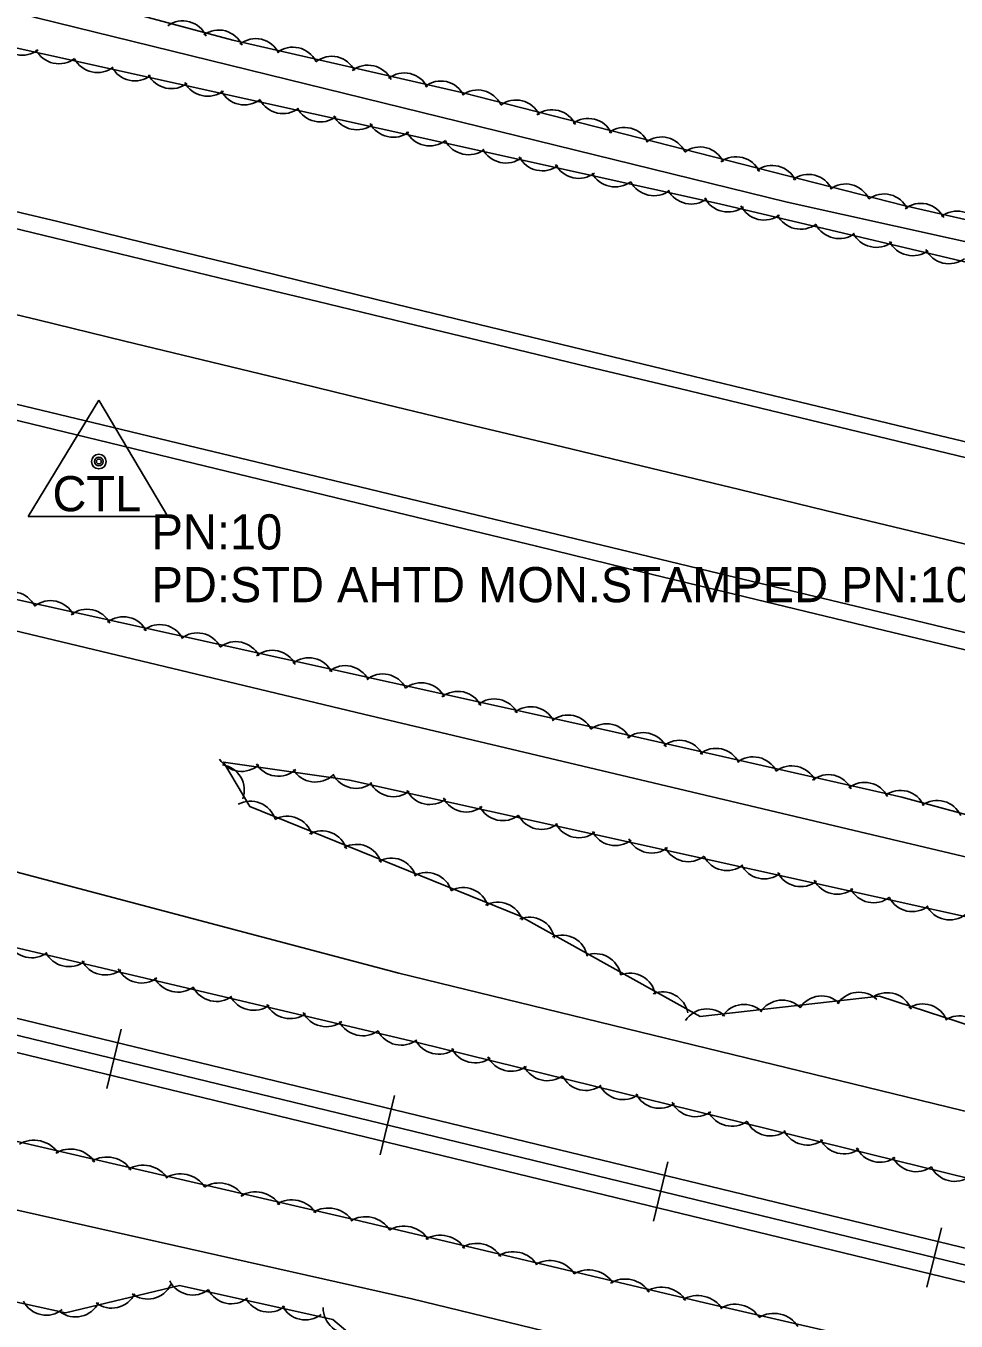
# Model space of a CAD drawing. Extents: x 1441650 to 1491889, y 345904 to 358319.
# Drawn here: x 1451853.3 to 1451985.6, y 352945.7 to 353129.9 of the extents above; entities that cross this region are included whole.
import ezdxf

# ---------------------------------------------------------------- set-up
doc = ezdxf.new("R2010")
doc.units = 0
for name, color, linetype in [('S_EDGE_PAVEMENT', 7, 'Continuous'), ('S_PAVEMENT_CROWN', 7, 'Continuous'), ('S_PRIMARY_CTL', 7, 'Continuous'), ('S_PRIMARY_CTL_ANNOT', 7, 'Continuous'), ('S_RAILROAD', 7, 'Continuous'), ('S_SHOULDER', 7, 'Continuous'), ('S_STREAM', 7, 'Continuous'), ('S_TREE', 7, 'Continuous')]:
    doc.layers.add(name, color=color, linetype=linetype)

msp = doc.modelspace()

# ---------------------------------------------------------------- linework, layer by layer
at = {"layer": 'S_EDGE_PAVEMENT'}
for points in [[(1451783.27, 353117.48), (1451795.88, 353114.44), (1451808.49, 353111.4), (1451820.7, 353108.49), (1451832.9, 353105.58), (1451845.11, 353102.67), (1451857.31, 353099.75), (1451869.83, 353096.73), (1451882.35, 353093.7), (1451894.87, 353090.67), (1451907.38, 353087.64), (1451920.35, 353084.53), (1451933.31, 353081.42), (1451946.28, 353078.32), (1451959.25, 353075.21), (1451982.98, 353069.48), (1452006.71, 353063.75), (1452019.76, 353060.6), (1452032.81, 353057.44), (1452045.86, 353054.28), (1452058.91, 353051.13), (1452072, 353047.96), (1452085.09, 353044.79), (1452098.18, 353041.61)], [(1451777.98, 353093.92), (1451790.47, 353090.88), (1451802.97, 353087.85), (1451815.21, 353084.91), (1451827.46, 353081.98), (1451839.71, 353079.05), (1451851.96, 353076.11), (1451864.17, 353073.17), (1451876.38, 353070.23), (1451888.6, 353067.29), (1451900.81, 353064.35), (1451913.59, 353061.27), (1451926.38, 353058.2), (1451939.16, 353055.12), (1451951.95, 353052.04), (1451975.89, 353046.27), (1451999.84, 353040.51), (1452013.23, 353037.27), (1452026.61, 353034.04), (1452040, 353030.81), (1452053.39, 353027.58), (1452066.24, 353024.5), (1452079.1, 353021.43), (1452091.95, 353018.36)]]:
    msp.add_lwpolyline(points, dxfattribs=at)
at = {"layer": 'S_PAVEMENT_CROWN'}
msp.add_lwpolyline([(1451780.05, 353106.21), (1451792.45, 353103.16), (1451804.86, 353100.12), (1451817.4, 353097.11), (1451829.94, 353094.1), (1451842.48, 353091.09), (1451855.02, 353088.08), (1451867.4, 353085.07), (1451879.77, 353082.07), (1451892.14, 353079.07), (1451904.51, 353076.07), (1451917.08, 353073.04), (1451929.66, 353070.01), (1451942.23, 353066.98), (1451954.8, 353063.95), (1451967.03, 353061), (1451979.27, 353058.05), (1451991.5, 353055.1)], dxfattribs=at)
at = {"layer": 'S_PRIMARY_CTL'}
for p, q in [((1451863.71, 353076.65), (1451853.68, 353060.13)), ((1451863.71, 353076.65), (1451873.54, 353060.13)), ((1451853.68, 353060.13), (1451873.54, 353060.13))]:
    msp.add_line(p, q, dxfattribs=at)
for radius in [1.04, 0.609, 0.344]:
    msp.add_circle((1451863.71, 353067.94), radius, dxfattribs=at)
at = {"layer": 'S_RAILROAD'}
for p, q in [((1451864.85, 352978.8), (1451866.89, 352987.23)), ((1451866.42, 352985.29), (1451866.4, 352985.19)), ((1451865.31, 352980.71), (1451865.32, 352980.75)), ((1451903.73, 352969.38), (1451905.77, 352977.81)), ((1451905.3, 352975.87), (1451905.28, 352975.77)), ((1451904.19, 352971.29), (1451904.2, 352971.33)), ((1451942.61, 352959.96), (1451944.65, 352968.39)), ((1451944.18, 352966.45), (1451944.15, 352966.35)), ((1451943.07, 352961.87), (1451943.08, 352961.91)), ((1451981.48, 352950.55), (1451983.53, 352958.98)), ((1451983.06, 352957.03), (1451983.03, 352956.93)), ((1451981.95, 352952.45), (1451981.96, 352952.49))]:
    msp.add_line(p, q, dxfattribs=at)
for points in [[(1452391.27, 352858.13), (1451315.37, 353118.79)], [(1452390.72, 352855.86), (1451314.82, 353116.52)], [(1452390.16, 352853.56), (1451314.26, 353114.21)], [(1451865.9, 352983.01), (1451865.87, 352983.02)], [(1451904.78, 352973.59), (1451904.75, 352973.6)], [(1451943.66, 352964.17), (1451943.63, 352964.18)], [(1451982.53, 352954.75), (1451982.51, 352954.76)]]:
    msp.add_lwpolyline(points, dxfattribs=at)
at = {"layer": 'S_SHOULDER'}
for points in [[(1451784.12, 353119.66), (1451796.45, 353116.64), (1451808.79, 353113.61), (1451821.06, 353110.72), (1451833.33, 353107.84), (1451845.59, 353104.95), (1451857.86, 353102.06), (1451870.4, 353099), (1451882.94, 353095.94), (1451895.48, 353092.87), (1451908.01, 353089.81), (1451920.95, 353086.67), (1451933.88, 353083.53), (1451946.81, 353080.4), (1451959.74, 353077.26), (1451983.41, 353071.6), (1452007.08, 353065.94), (1452020.17, 353062.81), (1452033.26, 353059.68), (1452046.34, 353056.55), (1452059.43, 353053.42), (1452072.45, 353050.18), (1452085.47, 353046.94), (1452098.49, 353043.7)], [(1451776.78, 353092.03), (1451789.4, 353088.96), (1451802.02, 353085.89), (1451814.3, 353082.92), (1451826.59, 353079.95), (1451838.88, 353076.98), (1451851.16, 353074.01), (1451863.47, 353071.03), (1451875.77, 353068.05), (1451888.08, 353065.07), (1451900.38, 353062.09), (1451913.16, 353058.99), (1451925.93, 353055.89), (1451938.71, 353052.79), (1451951.48, 353049.7), (1451975.44, 353043.94), (1451999.4, 353038.19), (1452012.81, 353034.93), (1452026.22, 353031.67), (1452039.63, 353028.41), (1452053.04, 353025.15), (1452065.84, 353022.05), (1452078.65, 353018.96), (1452091.46, 353015.87)]]:
    msp.add_lwpolyline(points, dxfattribs=at)
at = {"layer": 'S_STREAM'}
for points in [[(1452445.19, 352960.92), (1452448.5, 352972.75), (1452448.23, 352981.93), (1452444.57, 352990.17), (1452433.3, 352993.25), (1452415.41, 352997.26), (1452378.65, 353003.82), (1452324.67, 353015.77), (1452282.93, 353026.78), (1452238.99, 353039.11), (1452155.9, 353057.5), (1452105.48, 353068.81), (1452050.85, 353084.26), (1452000.32, 353096.23), (1451961.6, 353104.8), (1451854.91, 353131.04), (1451766.04, 353157.21)], [(1452109.57, 352946.22), (1452091.57, 352950.96), (1451986.3, 352975.72), (1451906.35, 352995.19), (1451767.48, 353031.94), (1451736.48, 353040.82), (1451750.21, 353055.92), (1451749.26, 353065.31), (1451760.74, 353064.8), (1451835.77, 353047.72), (1451901.35, 353032.04), (1451989.35, 353011.18), (1452041.05, 352997.24), (1452069.23, 352991.2), (1452108.22, 352979.84), (1452119.37, 352976.87)], [(1451761.2, 352984.03), (1451829.92, 352966.49), (1451908.23, 352948.92), (1451988.74, 352929.34), (1452105.17, 352903.77), (1452208.98, 352879), (1452288.64, 352859.53), (1452296.9, 352854.48), (1452309.22, 352851.75), (1452341.4, 352846.85)]]:
    msp.add_lwpolyline(points, dxfattribs=at)
at = {"layer": 'S_TREE'}
for points in [[(1451842.5, 353138.67), (1451882.78, 353127.85), (1451915.54, 353120.36), (1451978.21, 353104.35), (1452002.07, 353098.89), (1452031.98, 353100.97), (1452056.87, 353104.1), (1452066.02, 353098.43), (1452087.42, 353079.53), (1452116.54, 353072.49)], [(1452429.49, 352965.49), (1452437.88, 352969.07), (1452439.81, 352977.76), (1452437.34, 352984.74), (1452427.24, 352990.22), (1452405.5, 352995.03), (1452379.5, 353000.79), (1452338.14, 353009.4), (1452310.5, 353013.5), (1452296.75, 353015.27), (1452257.56, 353023.53), (1452218.85, 353038.77), (1452176.21, 353048.21), (1452120.8, 353061.85), (1452077.66, 353072.61), (1452041.75, 353083.37), (1451951.96, 353104.58), (1451836.47, 353130.15), (1451825.19, 353132.83)], [(1452399.14, 352860.23), (1452392.79, 352867.03), (1452382.12, 352869.59), (1452327.3, 352883.47), (1452173.6, 352920.35), (1452113.09, 352935.02), (1451909.03, 352985.34), (1451768.73, 353018.48), (1451597.59, 353062.21), (1451520.63, 353079.57), (1451497.6, 353087.01), (1451451.58, 353107.05), (1451431.16, 353111.57), (1451407.97, 353109.12), (1451350.29, 353121.94)], [(1451327.8, 353097.43), (1451402.02, 353075.91), (1451483.15, 353063.22), (1451576.93, 353036.02), (1451646.54, 353020.05), (1451689.99, 353010.43), (1451796.02, 352984.25), (1451899.97, 352960.18), (1451949.9, 352948.34), (1452006.53, 352935.3), (1452073.14, 352918.73), (1452124.03, 352905.6), (1452167.72, 352893.63), (1452197.97, 352887.99), (1452238.01, 352878.56), (1452281.14, 352868.99), (1452322.62, 352858.1), (1452348, 352852.48), (1452371.02, 352846.3), (1452385.26, 352842.85), (1452392.41, 352843.39), (1452396.82, 352844.8), (1452398.6, 352846.57)], [(1451756.76, 353072.92), (1451807.16, 353058.25), (1451866.54, 353045.1), (1451936.11, 353029.7), (1451977.89, 353020.21), (1452015.38, 353010.02), (1452054.5, 353001.3), (1452108.24, 352989.27)], [(1452103.73, 352977.64), (1452080.41, 352979.97), (1452042.94, 352989.96), (1452000.57, 353000.22), (1451939.2, 353013.81), (1451899.38, 353022.62), (1451881.43, 353025.21), (1451885.19, 353018.89), (1451923.55, 353003.35), (1451949.24, 352989.05), (1451974.75, 352991.94), (1451992.76, 352986.08), (1452003.91, 352976.56), (1452027.47, 352979.69), (1452048.56, 352975.18), (1452071.11, 352968.43), (1452109.87, 352950.96)], [(1452091.94, 352900.54), (1452069.93, 352896.14), (1452043.61, 352882.16), (1452020.94, 352887.17), (1451990.24, 352893.97), (1451963.33, 352905.38), (1451917.06, 352921.58), (1451910.69, 352934.41), (1451896.97, 352945.96), (1451875.2, 352950.78), (1451858.99, 352946.93), (1451844.89, 352949.99), (1451833.41, 352962.9), (1451811.35, 352963.14), (1451805.02, 352950.99), (1451762.83, 352955.93)]]:
    msp.add_lwpolyline(points, dxfattribs=at)
for centre, major_axis, ratio, start_param, end_param in [((1451875.66, 353126.94), (-1.09, 3.48), 0.995778, 4.831799, 6.605), ((1451880.77, 353125.64), (-1.09, 3.48), 0.995778, 4.831799, 6.605), ((1451886.02, 353124.42), (-3.4, 1.31), 0.998778, 3.968517, 5.741717), ((1451852.79, 353129.25), (3.53, -0.9), 0.969335, 3.8583, 5.6315), ((1451857.99, 353128.03), (3.53, -0.9), 0.969335, 3.8583, 5.6315), ((1451891.32, 353123.21), (-3.4, 1.31), 0.998778, 3.968517, 5.741717), ((1451863.49, 353126.78), (3.53, -0.9), 0.969335, 3.8583, 5.6315), ((1451896.82, 353121.91), (-3.4, 1.31), 0.998778, 3.968517, 5.741717), ((1451868.8, 353125.6), (3.53, -0.9), 0.969335, 3.8583, 5.6315), ((1451873.99, 353124.49), (3.53, -0.9), 0.969335, 3.8583, 5.6315), ((1451902, 353120.65), (-3.4, 1.31), 0.998778, 3.968517, 5.741717), ((1451907.16, 353119.55), (-3.4, 1.31), 0.998778, 3.968517, 5.741717), ((1451879.16, 353123.41), (3.53, -0.9), 0.969335, 3.8583, 5.6315), ((1451912.34, 353118.4), (-3.4, 1.31), 0.998778, 3.968517, 5.741717), ((1451917.57, 353117.13), (-3.48, 1.08), 0.998791, 3.877829, 5.651029), ((1451884.36, 353122.19), (3.53, -0.9), 0.969335, 3.8583, 5.6315), ((1451889.86, 353120.94), (3.53, -0.9), 0.969335, 3.8583, 5.6315), ((1451923.03, 353115.7), (-3.48, 1.08), 0.998791, 3.877829, 5.651029), ((1451895.17, 353119.76), (3.53, -0.9), 0.969335, 3.8583, 5.6315), ((1451928.18, 353114.31), (-3.48, 1.08), 0.998791, 3.877829, 5.651029), ((1451900.36, 353118.65), (3.53, -0.9), 0.969335, 3.8583, 5.6315), ((1451905.53, 353117.58), (3.53, -0.9), 0.969335, 3.8583, 5.6315), ((1451933.32, 353113.08), (-3.48, 1.08), 0.998791, 3.877829, 5.651029), ((1451938.46, 353111.8), (-3.48, 1.08), 0.998791, 3.877829, 5.651029), ((1451910.72, 353116.36), (3.53, -0.9), 0.969335, 3.8583, 5.6315), ((1451916.23, 353115.1), (3.53, -0.9), 0.969335, 3.8583, 5.6315), ((1451943.73, 353110.45), (-3.48, 1.08), 0.998791, 3.877829, 5.651029), ((1451921.54, 353113.92), (3.53, -0.9), 0.969335, 3.8583, 5.6315), ((1451949.2, 353109.02), (-3.48, 1.08), 0.998791, 3.877829, 5.651029), ((1451926.73, 353112.81), (3.53, -0.9), 0.969335, 3.8583, 5.6315), ((1451931.9, 353111.74), (3.53, -0.9), 0.969335, 3.8583, 5.6315), ((1451954.35, 353107.63), (-3.48, 1.08), 0.998791, 3.877829, 5.651029), ((1451959.48, 353106.39), (-3.48, 1.08), 0.998791, 3.877829, 5.651029), ((1451937.09, 353110.52), (3.53, -0.9), 0.969335, 3.8583, 5.6315), ((1451964.63, 353105.12), (-3.48, 1.08), 0.998791, 3.877829, 5.651029), ((1451942.6, 353109.27), (3.53, -0.9), 0.969335, 3.8583, 5.6315), ((1451947.91, 353108.09), (3.53, -0.9), 0.969335, 3.8583, 5.6315), ((1451969.9, 353103.77), (-3.48, 1.08), 0.998791, 3.877829, 5.651029), ((1451975.37, 353102.34), (-3.48, 1.08), 0.998791, 3.877829, 5.651029), ((1451953.14, 353106.96), (3.58, -0.69), 0.969283, 3.781707, 5.554908), ((1451958.3, 353105.81), (3.58, -0.69), 0.969283, 3.781707, 5.554908), ((1451980.6, 353101.01), (-3.55, 0.81), 0.998803, 3.825789, 5.598989), ((1451963.48, 353104.51), (3.58, -0.69), 0.969283, 3.781707, 5.554908), ((1451985.77, 353099.9), (-3.55, 0.81), 0.998803, 3.825789, 5.598989), ((1451968.96, 353103.18), (3.58, -0.69), 0.969283, 3.781707, 5.554908), ((1451974.26, 353101.93), (3.58, -0.69), 0.969283, 3.781707, 5.554908), ((1451979.43, 353100.74), (3.58, -0.69), 0.969283, 3.781707, 5.554908), ((1451984.58, 353099.6), (3.58, -0.69), 0.969283, 3.781707, 5.554908), ((1451851.33, 353045.79), (-3.56, 0.79), 0.997457, 3.825789, 5.598989), ((1451856.84, 353044.53), (-3.56, 0.79), 0.997457, 3.825789, 5.598989), ((1451862.03, 353043.31), (-3.56, 0.79), 0.997457, 3.825789, 5.598989), ((1451867.21, 353042.24), (-3.5, 1.01), 0.997447, 3.889288, 5.662488), ((1451872.39, 353041.13), (-3.5, 1.01), 0.997447, 3.889288, 5.662488), ((1451877.71, 353039.95), (-3.5, 1.01), 0.997447, 3.889288, 5.662488), ((1451883.21, 353038.7), (-3.5, 1.01), 0.997447, 3.889288, 5.662488), ((1451888.4, 353037.47), (-3.5, 1.01), 0.997447, 3.889288, 5.662488), ((1451893.58, 353036.4), (-3.5, 1.01), 0.997447, 3.889288, 5.662488), ((1451898.76, 353035.29), (-3.5, 1.01), 0.997447, 3.889288, 5.662488), ((1451904.08, 353034.11), (-3.5, 1.01), 0.997447, 3.889288, 5.662488), ((1451909.58, 353032.86), (-3.5, 1.01), 0.997447, 3.889288, 5.662488), ((1451914.77, 353031.63), (-3.5, 1.01), 0.997447, 3.889288, 5.662488), ((1451919.95, 353030.56), (-3.5, 1.01), 0.997447, 3.889288, 5.662488), ((1451925.13, 353029.45), (-3.5, 1.01), 0.997447, 3.889288, 5.662488), ((1451930.45, 353028.27), (-3.5, 1.01), 0.997447, 3.889288, 5.662488), ((1451935.93, 353027.02), (-3.64, -0.23), 0.997233, 3.537634, 5.310834), ((1451941.12, 353025.77), (-3.64, -0.23), 0.997233, 3.537634, 5.310834), ((1451946.28, 353024.67), (-3.64, -0.23), 0.997233, 3.537634, 5.310834), ((1451951.46, 353023.53), (-3.64, -0.23), 0.997233, 3.537634, 5.310834), ((1451884.01, 353027.52), (3.61, -0.52), 0.997482, 3.825789, 5.598989), ((1451956.77, 353022.32), (-3.64, -0.23), 0.997233, 3.537634, 5.310834), ((1451880.76, 353021.22), (-1.86, 3.13), 0.998734, 3.825789, 5.598989), ((1451889.24, 353026.84), (3.61, -0.52), 0.997482, 3.825789, 5.598989), ((1451894.51, 353026.01), (3.61, -0.52), 0.997482, 3.825789, 5.598989), ((1451900.29, 353025.11), (3.6, -0.57), 0.997447, 3.763566, 5.536766), ((1451962.26, 353021.04), (-3.64, -0.23), 0.997233, 3.537634, 5.310834), ((1451967.45, 353019.79), (-3.64, -0.23), 0.997233, 3.537634, 5.310834), ((1451905.6, 353023.93), (3.6, -0.57), 0.997447, 3.763566, 5.536766), ((1451972.61, 353018.69), (-3.64, -0.23), 0.997233, 3.537634, 5.310834), ((1451885.3, 353016.02), (-3.37, 1.4), 0.997505, 3.833875, 5.607075), ((1451910.78, 353022.82), (3.6, -0.57), 0.997447, 3.763566, 5.536766), ((1451915.96, 353021.75), (3.6, -0.57), 0.997447, 3.763566, 5.536766), ((1451977.69, 353017.55), (-3.52, 0.96), 0.997457, 3.825789, 5.598989), ((1451982.94, 353016.12), (-3.52, 0.96), 0.997457, 3.825789, 5.598989), ((1451921.15, 353020.52), (3.6, -0.57), 0.997447, 3.763566, 5.536766), ((1451890.52, 353013.87), (-3.37, 1.4), 0.997505, 3.833875, 5.607075), ((1451926.66, 353019.27), (3.6, -0.57), 0.997447, 3.763566, 5.536766), ((1451931.97, 353018.09), (3.6, -0.57), 0.997447, 3.763566, 5.536766), ((1451895.44, 353011.8), (-3.37, 1.4), 0.997505, 3.833875, 5.607075), ((1451937.15, 353016.98), (3.6, -0.57), 0.997447, 3.763566, 5.536766), ((1451942.33, 353015.91), (3.56, -0.79), 0.997457, 3.825789, 5.598989), ((1451900.36, 353009.88), (-3.37, 1.4), 0.997505, 3.833875, 5.607075), ((1451947.52, 353014.69), (3.56, -0.79), 0.997457, 3.825789, 5.598989), ((1451905.29, 353007.93), (-3.37, 1.4), 0.997505, 3.833875, 5.607075), ((1451953.03, 353013.43), (3.56, -0.79), 0.997457, 3.825789, 5.598989), ((1451958.34, 353012.25), (3.56, -0.79), 0.997457, 3.825789, 5.598989), ((1451910.33, 353005.88), (-3.37, 1.4), 0.997505, 3.833875, 5.607075), ((1451963.52, 353011.14), (3.56, -0.79), 0.997457, 3.825789, 5.598989), ((1451915.55, 353003.73), (-3.37, 1.4), 0.997505, 3.833875, 5.607075), ((1451968.7, 353010.07), (3.56, -0.79), 0.997457, 3.825789, 5.598989), ((1451973.89, 353008.85), (3.56, -0.79), 0.997457, 3.825789, 5.598989), ((1451920.47, 353001.66), (-3.37, 1.4), 0.997505, 3.833875, 5.607075), ((1451979.4, 353007.59), (3.56, -0.79), 0.997457, 3.825789, 5.598989), ((1451924.93, 352999.54), (-3.18, 1.77), 0.997627, 3.825789, 5.598989), ((1451984.71, 353006.42), (3.56, -0.79), 0.997457, 3.825789, 5.598989), ((1451854.12, 353000.94), (3.51, -0.98), 0.97372, 3.86825, 5.64145), ((1451929.59, 352996.99), (-3.18, 1.77), 0.997627, 3.825789, 5.598989), ((1451859.41, 352999.69), (3.51, -0.98), 0.97372, 3.86825, 5.64145), ((1451934.34, 352994.35), (-3.18, 1.77), 0.997627, 3.825789, 5.598989), ((1451864.58, 352998.5), (3.51, -0.98), 0.97372, 3.86825, 5.64145), ((1451869.74, 352997.36), (3.51, -0.98), 0.97372, 3.86825, 5.64145), ((1451874.92, 352996.06), (3.51, -0.98), 0.97372, 3.86825, 5.64145), ((1451939.26, 352991.57), (-3.18, 1.77), 0.997627, 3.825789, 5.598989), ((1451880.4, 352994.73), (3.51, -0.98), 0.97372, 3.86825, 5.64145), ((1451885.7, 352993.48), (3.51, -0.98), 0.97372, 3.86825, 5.64145), ((1451943.88, 352988.91), (-3.18, 1.77), 0.997627, 3.825789, 5.598989), ((1451966.49, 352988.33), (-3.62, -0.41), 0.997766, 3.825789, 5.598989), ((1451971.8, 352988.86), (-3.62, -0.41), 0.997766, 3.825789, 5.598989), ((1451975.84, 352988.79), (-3.38, 1.37), 0.997455, 3.895823, 5.669023), ((1451890.87, 352992.29), (3.51, -0.98), 0.97372, 3.86825, 5.64145), ((1451950.2, 352986.49), (-3.62, -0.41), 0.997766, 3.825789, 5.598989), ((1451955.47, 352987.12), (-3.62, -0.41), 0.997766, 3.825789, 5.598989), ((1451960.88, 352987.73), (-3.62, -0.41), 0.997766, 3.825789, 5.598989), ((1451980.89, 352987.19), (-3.38, 1.37), 0.997455, 3.895823, 5.669023), ((1451896.02, 352991.15), (3.51, -0.98), 0.97372, 3.86825, 5.64145), ((1451901.2, 352989.85), (3.51, -0.98), 0.97372, 3.86825, 5.64145), ((1451986.07, 352985.5), (-3.38, 1.37), 0.997455, 3.895823, 5.669023), ((1451906.69, 352988.52), (3.51, -0.98), 0.97372, 3.86825, 5.64145), ((1451912.01, 352987.24), (3.54, -0.85), 0.973758, 3.81871, 5.591911), ((1451917.17, 352986), (3.54, -0.85), 0.973758, 3.81871, 5.591911), ((1451922.31, 352984.81), (3.54, -0.85), 0.973758, 3.81871, 5.591911), ((1451927.47, 352983.46), (3.54, -0.85), 0.973758, 3.81871, 5.591911), ((1451932.95, 352982.08), (3.54, -0.85), 0.973758, 3.81871, 5.591911), ((1451938.23, 352980.77), (3.54, -0.85), 0.973758, 3.81871, 5.591911), ((1451943.39, 352979.54), (3.54, -0.85), 0.973758, 3.81871, 5.591911), ((1451948.53, 352978.34), (3.54, -0.85), 0.973758, 3.81871, 5.591911), ((1451953.7, 352977), (3.54, -0.85), 0.973758, 3.81871, 5.591911), ((1451959.17, 352975.61), (3.54, -0.85), 0.973758, 3.81871, 5.591911), ((1451964.45, 352974.31), (3.54, -0.85), 0.973758, 3.81871, 5.591911), ((1451854.75, 352968.32), (-3.53, 0.9), 0.854277, 3.852479, 5.62568), ((1451859.93, 352967.05), (-3.53, 0.9), 0.854277, 3.852479, 5.62568), ((1451969.61, 352973.07), (3.54, -0.85), 0.973758, 3.81871, 5.591911), ((1451974.76, 352971.87), (3.54, -0.85), 0.973758, 3.81871, 5.591911), ((1451865.09, 352965.92), (-3.53, 0.9), 0.854277, 3.852479, 5.62568), ((1451870.27, 352964.76), (-3.53, 0.9), 0.854277, 3.852479, 5.62568), ((1451979.92, 352970.53), (3.54, -0.85), 0.973758, 3.81871, 5.591911), ((1451875.57, 352963.53), (-3.53, 0.9), 0.854277, 3.852479, 5.62568), ((1451985.39, 352969.15), (3.54, -0.85), 0.973758, 3.81871, 5.591911), ((1451881.06, 352962.23), (-3.53, 0.9), 0.854277, 3.852479, 5.62568), ((1451886.24, 352960.96), (-3.53, 0.9), 0.854277, 3.852479, 5.62568), ((1451891.4, 352959.83), (-3.53, 0.9), 0.854277, 3.852479, 5.62568), ((1451896.58, 352958.67), (-3.53, 0.9), 0.854277, 3.852479, 5.62568), ((1451901.83, 352957.44), (-3.56, 0.79), 0.854303, 3.807484, 5.580685), ((1451907.32, 352956.1), (-3.56, 0.79), 0.854303, 3.807484, 5.580685), ((1451912.49, 352954.81), (-3.56, 0.79), 0.854303, 3.807484, 5.580685), ((1451917.65, 352953.65), (-3.56, 0.79), 0.854303, 3.807484, 5.580685), ((1451922.82, 352952.46), (-3.56, 0.79), 0.854303, 3.807484, 5.580685), ((1451928.11, 352951.2), (-3.56, 0.79), 0.854303, 3.807484, 5.580685), ((1451877.06, 352953.09), (3.56, -0.79), 0.999878, 3.825789, 5.598989), ((1451933.6, 352949.87), (-3.56, 0.79), 0.854303, 3.807484, 5.580685), ((1451938.77, 352948.58), (-3.56, 0.79), 0.854303, 3.807484, 5.580685), ((1451865.54, 352951.22), (3.54, 0.84), 0.999891, 3.825789, 5.598989), ((1451870.66, 352952.51), (3.54, 0.84), 0.999891, 3.825789, 5.598989), ((1451882.57, 352951.84), (3.56, -0.79), 0.999878, 3.825789, 5.598989), ((1451943.93, 352947.42), (-3.56, 0.79), 0.854303, 3.807484, 5.580685), ((1451856.24, 352950.22), (3.56, -0.77), 0.999878, 3.825789, 5.598989), ((1451860.38, 352949.96), (3.54, 0.84), 0.999891, 3.825789, 5.598989), ((1451887.88, 352950.66), (3.56, -0.79), 0.999878, 3.825789, 5.598989), ((1451893.07, 352949.55), (3.56, -0.79), 0.999878, 3.825789, 5.598989), ((1451949.09, 352946.23), (-3.56, 0.79), 0.854303, 3.807484, 5.580685), ((1451954.4, 352945), (-3.57, 0.71), 0.854156, 3.790351, 5.563551), ((1451899.26, 352947.6), (3.14, -1.86), 0.999911, 3.660196, 5.433397), ((1451959.89, 352943.71), (-3.57, 0.71), 0.854156, 3.790351, 5.563551)]:
    msp.add_ellipse(centre, major_axis=major_axis, ratio=ratio, start_param=start_param, end_param=end_param, dxfattribs=at)

# ---------------------------------------------------------------- texts
at = {"layer": 'S_PRIMARY_CTL'}
msp.add_text('CTL', height=5, rotation=360, dxfattribs=at).set_placement((1451857.12, 353060.87))
at = {"layer": 'S_PRIMARY_CTL_ANNOT'}
for s, p in [('PN:10', (1451871.21, 353055.44)), ('PD:STD AHTD MON.STAMPED PN:10 JOB 050264', (1451871.21, 353047.94))]:
    msp.add_text(s, height=5, dxfattribs=at).set_placement(p)

doc.saveas('drawing.dxf')
